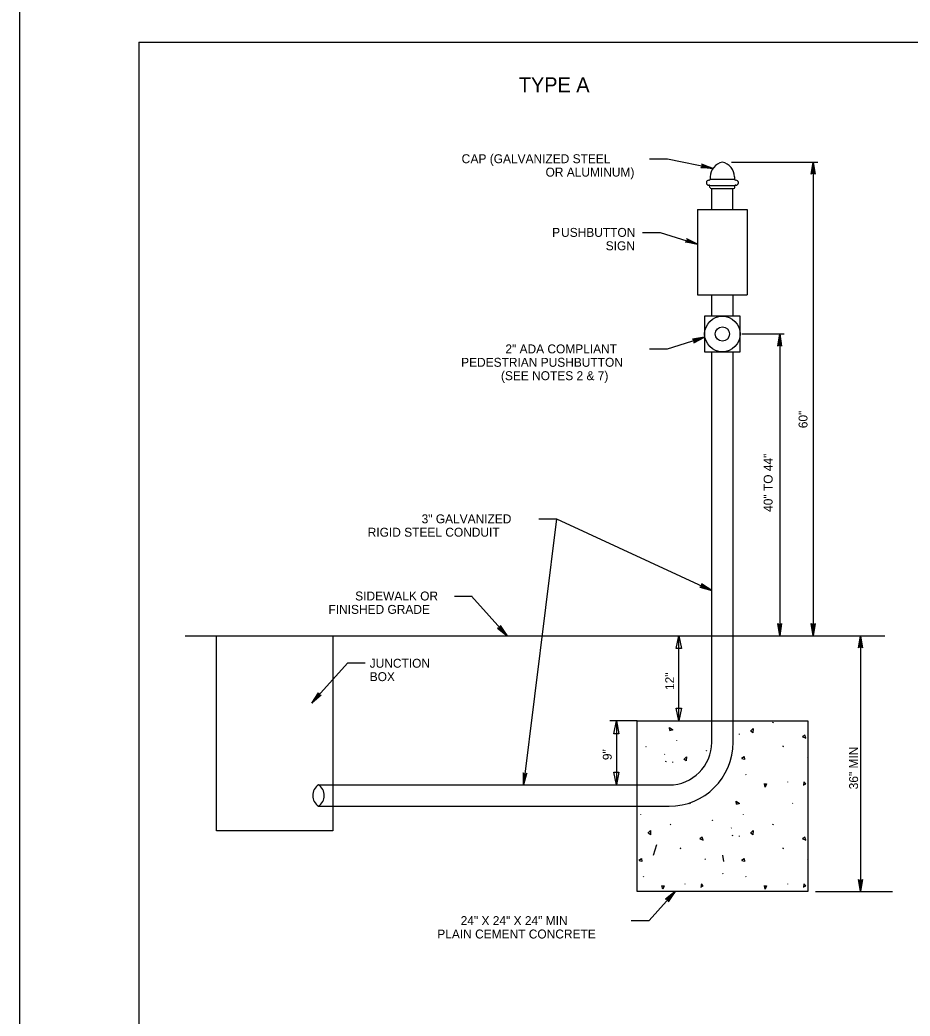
# Model space of a CAD drawing. Extents: x 36 to 940, y -1166 to 1210.
# Drawn here: x 35.9 to 335.1, y 274 to 608.7 of the extents above; entities that cross this region are included whole.
import ezdxf

# ---------------------------------------------------------------- set-up
doc = ezdxf.new("R2010")
doc.units = 0
for name, color, linetype in [('1', 7, 'Continuous'), ('2', 7, 'Continuous'), ('Default', 7, 'Continuous'), ('PLT-BNDY', 7, 'Continuous')]:
    doc.layers.add(name, color=color, linetype=linetype)

msp = doc.modelspace()

# ---------------------------------------------------------------- linework, layer by layer
at = {"layer": '1'}
for q in [(861.86, 601.17), (75.86, 37.17)]:
    msp.add_line((75.86, 601.17), q, dxfattribs=at)
at = {"layer": '2'}
for p, q in [((253.55, 562.03), (268.91, 558.82)), ((251.16, 537.28), (263.67, 533.38)), ((253.55, 498.13), (266.06, 502.03)), ((216.28, 441.04), (205.15, 351.63)), ((216.28, 441.04), (268.4, 416.95)), ((187.65, 415.11), (199.59, 401.8)), ((145.96, 392.51), (134.02, 379.19)), ((247.41, 306.04), (256.12, 315.83))]:
    msp.add_line(p, q, dxfattribs=at)
for points in [[(265.22, 560.07), (265.3, 559.77), (268.89, 558.79), (265.22, 560.07), (265.06, 560.28), (268.89, 558.79), (265.22, 559.39), (265.03, 559.15), (268.89, 558.79), (264.79, 559.01), (265.03, 559.15)], [(302.09, 557.05), (302.37, 557.2), (302.57, 560.91), (302.09, 557.05), (301.92, 556.86), (302.57, 560.91), (302.76, 557.2), (303.03, 557.07), (302.57, 560.91), (303.22, 556.86), (303.03, 557.07)], [(260.14, 535), (260.19, 534.69), (263.67, 533.38), (260.14, 535), (260, 535.22), (263.67, 533.38), (260.08, 534.32), (259.86, 534.1), (263.67, 533.38), (259.61, 533.99), (259.86, 534.1)], [(290.82, 499.29), (291.09, 499.43), (291.3, 503.15), (290.82, 499.29), (290.65, 499.09), (291.3, 503.15), (291.48, 499.44), (291.76, 499.3), (291.3, 503.15), (291.94, 499.09), (291.76, 499.3)], [(262.53, 500.4), (262.58, 500.71), (266.06, 502.03), (262.53, 500.4), (262.39, 500.18), (266.06, 502.03), (262.46, 501.08), (262.25, 501.3), (266.06, 502.03), (262, 501.42), (262.25, 501.3)], [(264.75, 418.12), (264.99, 418.31), (268.45, 416.92), (264.75, 418.12), (264.49, 418.05), (268.45, 416.92), (265.16, 418.66), (265.16, 418.97), (268.45, 416.92), (265.05, 419.23), (265.16, 418.97)], [(196.7, 404.32), (197.01, 404.4), (199.63, 401.76), (196.7, 404.32), (196.44, 404.36), (199.63, 401.76), (197.3, 404.66), (197.42, 404.94), (199.63, 401.76), (197.42, 405.22), (197.42, 404.94)], [(291.78, 405.62), (291.5, 405.48), (291.3, 401.76), (291.78, 405.62), (291.95, 405.82), (291.3, 401.76), (291.12, 405.48), (290.84, 405.61), (291.3, 401.76), (290.65, 405.82), (290.84, 405.61)], [(303.06, 405.62), (302.78, 405.48), (302.57, 401.76), (303.06, 405.62), (303.23, 405.82), (302.57, 401.76), (302.39, 405.48), (302.11, 405.61), (302.57, 401.76), (301.93, 405.82), (302.11, 405.61)], [(317.96, 397.9), (318.24, 398.05), (318.44, 401.76), (317.96, 397.9), (317.79, 397.71), (318.44, 401.76), (318.63, 398.05), (318.9, 397.91), (318.44, 401.76), (319.09, 397.71), (318.9, 397.91)], [(136.91, 381.71), (136.6, 381.79), (133.98, 379.15), (136.91, 381.71), (137.17, 381.75), (133.98, 379.15), (136.31, 382.05), (136.19, 382.33), (133.98, 379.15), (136.19, 382.61), (136.19, 382.33)], [(205.18, 355.52), (205.44, 355.34), (205.15, 351.63), (205.18, 355.52), (205.04, 355.74), (205.15, 351.63), (205.82, 355.29), (206.12, 355.38), (205.15, 351.63), (206.33, 355.57), (206.12, 355.38)], [(318.93, 319.68), (318.65, 319.54), (318.44, 315.82), (318.93, 319.68), (319.1, 319.88), (318.44, 315.82), (318.26, 319.53), (317.98, 319.67), (318.44, 315.82), (317.8, 319.88), (317.98, 319.67)], [(253.93, 312.61), (253.81, 312.91), (256.12, 315.83), (253.93, 312.61), (253.92, 312.35), (256.12, 315.83), (253.52, 313.17), (253.23, 313.25), (256.12, 315.83), (252.95, 313.21), (253.23, 313.25)]]:
    msp.add_lwpolyline(points, dxfattribs=at)
at = {"layer": 'Default'}
for p, q in [((247.55, 562.03), (253.55, 562.03)), ((275.11, 560.91), (304.07, 560.91)), ((267.97, 555.96), (267.97, 555.22)), ((276.09, 555.96), (276.09, 555.22)), ((302.57, 558.13), (302.57, 401.76)), ((267.49, 554.82), (267.55, 554.82)), ((267.65, 553.13), (267.49, 553.13)), ((267.86, 552.38), (267.86, 552.93)), ((276.19, 552.38), (276.19, 552.93)), ((276.56, 553.13), (276.4, 553.13)), ((276.5, 554.82), (276.56, 554.82)), ((277.4, 553.92), (277.4, 554.03)), ((268.28, 551.98), (275.78, 551.98)), ((268.52, 545), (268.52, 551.98)), ((275.53, 545), (275.53, 551.98)), ((263.67, 545), (280.38, 545)), ((263.67, 545), (263.67, 516.35)), ((280.38, 545), (280.38, 516.35)), ((245.16, 537.28), (251.16, 537.28)), ((263.67, 516.35), (280.38, 516.35)), ((278.53, 503.15), (292.8, 503.15)), ((291.3, 503.15), (291.3, 401.76)), ((247.55, 498.13), (253.55, 498.13)), ((266.06, 497.18), (278, 497.18)), ((268.45, 401.76), (268.45, 497.18)), ((275.61, 401.76), (275.61, 497.18)), ((210.28, 441.04), (216.28, 441.04)), ((181.95, 415.11), (187.95, 415.11)), ((257.37, 373.12), (257.37, 401.76)), ((268.45, 365.95), (268.45, 401.76)), ((275.61, 365.95), (275.61, 401.76)), ((299.72, 401.76), (307.48, 401.76)), ((318.44, 401.76), (318.44, 315.82)), ((151.96, 392.51), (145.96, 392.51)), ((243.41, 373.12), (234.24, 373.12)), ((236.39, 373.12), (236.39, 351.63)), ((288.97, 372.55), (289.14, 372.69)), ((289.14, 372.69), (289, 372.48)), ((277.83, 368.61), (277.79, 368.83)), ((256.67, 366.45), (256.71, 366.59)), ((243.47, 364.52), (243.54, 364.59)), ((246.43, 364.44), (246.25, 364.48)), ((246.32, 364.59), (246.43, 364.44)), ((252.56, 361.9), (252.63, 361.97)), ((266.55, 363.08), (266.73, 363.23)), ((266.73, 363.23), (266.59, 363.01)), ((292.33, 364.64), (292.55, 364.53)), ((292.58, 364.53), (292.37, 364.71)), ((253.05, 359.36), (253.16, 359.72)), ((255.42, 359.14), (255.38, 359.36)), ((300.7, 360.93), (300.6, 361.02)), ((280.05, 354.93), (279.94, 355.15)), ((136.24, 351.63), (254.12, 351.63)), ((294.01, 352.6), (294.01, 352.68)), ((261.09, 345.36), (261.27, 345.5)), ((295.58, 345.36), (295.76, 345.5)), ((136.24, 344.47), (254.12, 344.47)), ((244.6, 341.65), (244.63, 341.79)), ((279.08, 341.65), (279.12, 341.79)), ((254.48, 338.28), (254.66, 338.42)), ((254.66, 338.42), (254.52, 338.21)), ((268.66, 339.71), (268.73, 339.79)), ((268.84, 339.64), (268.66, 339.68)), ((268.73, 339.79), (268.84, 339.64)), ((288.97, 338.28), (289.14, 338.42)), ((289.14, 338.42), (289, 338.21)), ((274.97, 337.1), (275.04, 337.17)), ((275.47, 334.56), (275.57, 334.92)), ((248.91, 328.05), (249.99, 331.63)), ((277.83, 334.34), (277.79, 334.56)), ((257.85, 330.37), (258.06, 330.26)), ((258.1, 330.26), (257.88, 330.44)), ((272.55, 325.9), (272.19, 328.05)), ((292.33, 330.37), (292.55, 330.26)), ((292.58, 330.26), (292.37, 330.44)), ((266.33, 326.57), (266.11, 326.75)), ((300.7, 326.66), (300.6, 326.75)), ((272.1, 321.77), (272.17, 321.92)), ((272.17, 321.92), (272.17, 321.74)), ((245.57, 320.66), (245.46, 320.88)), ((259.53, 318.34), (259.53, 318.41)), ((280.05, 320.66), (279.94, 320.88)), ((294.01, 318.34), (294.01, 318.41)), ((303.33, 315.82), (329.25, 315.82)), ((241.41, 306.04), (247.41, 306.04))]:
    msp.add_line(p, q, dxfattribs=at)
for points in [[(268.45, 509.12), (268.45, 516.35)], [(275.61, 509.12), (275.61, 516.35)], [(278, 497.18), (278, 509.12), (266.06, 509.12), (266.06, 497.18), (266.06, 497.18)], [(91.44, 401.76), (275.61, 401.76), (326.66, 401.76)], [(141.07, 401.76), (141.07, 336.24), (101.93, 336.24), (101.93, 401.76), (141.07, 401.76)], [(243.41, 373.12), (300.7, 373.12), (300.7, 315.82), (243.41, 315.82), (243.41, 373.12)], [(254.31, 369.96), (254.24, 370.96), (255.38, 370.14), (254.24, 369.81)], [(281.48, 369.69), (282.38, 370.58), (282.31, 369.18), (281.62, 369.69)], [(298.85, 367.86), (300.07, 367.36), (299.74, 368.32), (298.99, 367.93)], [(259.07, 360.22), (259.97, 361.11), (259.89, 359.72), (259.21, 360.22)], [(278.44, 360.63), (279.33, 361.2), (279.44, 360.16), (278.55, 360.41)], [(285.99, 352.03), (286.89, 352.03), (286.46, 350.89), (286.14, 351.96)], [(299.34, 351.66), (300.09, 352.05), (299.44, 352.62), (299.26, 351.48)], [(276.72, 345.16), (276.65, 346.16), (277.79, 345.34), (276.65, 345.01)], [(247, 335.42), (247.89, 336.31), (247.82, 334.92), (247.14, 335.42)], [(281.48, 335.42), (282.38, 336.31), (282.31, 334.92), (281.62, 335.42)], [(264.37, 333.59), (265.58, 333.09), (265.26, 334.06), (264.51, 333.66)], [(298.85, 333.59), (300.07, 333.09), (299.74, 334.06), (298.99, 333.66)], [(243.95, 326.36), (244.85, 326.93), (244.96, 325.89), (244.06, 326.14)], [(278.44, 326.36), (279.33, 326.93), (279.44, 325.89), (278.55, 326.14)], [(264.85, 317.39), (265.6, 317.78), (264.96, 318.36), (264.78, 317.21)], [(299.34, 317.39), (300.09, 317.78), (299.44, 318.36), (299.26, 317.21)], [(251.51, 317.76), (252.4, 317.76), (251.98, 316.62), (251.65, 317.69)], [(285.99, 317.76), (286.89, 317.76), (286.46, 316.62), (286.14, 317.69)]]:
    msp.add_lwpolyline(points, dxfattribs=at)
for points in [[(256.51, 397.47), (257.37, 401.76), (258.23, 397.47)], [(258.23, 377.41), (257.37, 373.12), (256.51, 377.41)], [(235.53, 368.82), (236.39, 373.12), (237.25, 368.82)], [(237.25, 355.93), (236.39, 351.63), (235.53, 355.93)]]:
    msp.add_lwpolyline(points, close=True, dxfattribs=at)
for radius in [5.97, 2.39]:
    msp.add_circle((272.03, 503.15), radius, dxfattribs=at)
for centre, radius, start, end in [((254.12, 365.95), 14.32, 270, 0), ((254.12, 365.95), 21.49, 270, 0), ((138.62, 348.05), 4.3, 123.5573, 236.4427), ((133.86, 348.05), 4.3, 303.5573, 56.4427)]:
    msp.add_arc(centre, radius, start, end, dxfattribs=at)
for centre, major_axis, ratio, start_param, end_param in [((273.39, 555.91), (5.43, 0), 0.952381, 1.825494, 3.132766), ((270.66, 555.91), (5.43, 0), 0.952381, 0.008827, 1.316099), ((267.49, 554.03), (0.833, 0), 0.952381, 1.570796, 3.141593), ((267.49, 553.92), (0.833, 0), 0.952381, 3.141593, 4.712389), ((267.55, 555.22), (0.417, 0), 0.952381, 4.712389, 6.283185), ((267.65, 552.93), (0.208, 0), 0.952381, 0, 1.570796), ((272.11, 553.13), (-4.46, 0), 0.026054, 0.212556, 2.780907), ((268.28, 552.38), (0.417, 0), 0.952381, 3.141593, 4.712389), ((272.03, 555.22), (-4.06, 0), 0.012269, 0, 3.141593), ((275.78, 552.38), (0.417, 0), 0.952381, 4.712389, 6.283185), ((276.5, 555.22), (0.417, 0), 0.952381, 3.141593, 4.712389), ((276.4, 552.93), (0.208, 0), 0.952381, 1.570796, 3.141593), ((276.56, 554.03), (0.833, 0), 0.952381, 0, 1.570796), ((276.56, 553.92), (0.833, 0), 0.952381, 4.712389, 6.283185)]:
    msp.add_ellipse(centre, major_axis=major_axis, ratio=ratio, start_param=start_param, end_param=end_param, dxfattribs=at)
at = {"layer": 'PLT-BNDY'}
msp.add_lwpolyline([(35.86, 616.17), (876.86, 616.17), (876.86, 22.17), (35.86, 22.17)], close=True, dxfattribs=at)

# ---------------------------------------------------------------- texts
at = {"layer": '2'}
msp.add_text('TYPE A', height=5, dxfattribs=at).set_placement((203.59, 584.39))
at = {"layer": 'Default'}
for s, rotation, p in [('C', 360, (184.35, 560.53)), ('AP (GALVANIZED STEEL', 360, (187.35, 560.53)), ('OR ALUMINUM)', 360, (212.58, 556.03)), ('P', 360, (214.8, 535.78)), ('USHBUTTON', 360, (217.8, 535.78)), ('SIGN', 360, (232.8, 531.28)), ('2" ADA COMPLIANT', 360, (199.07, 496.63)), ('PEDESTRIAN PUSHBUTTON', 360, (184.19, 492.13)), ('(SEE NOTES 2 & 7)', 360, (197.58, 487.63)), (' 60"', 90, (300.64, 470.38)), ('40" TO 44"', 90, (288.91, 443.37)), ('3" GALVANIZED', 360, (170.91, 439.54)), ('RIGID STEEL CONDUIT', 360, (152.79, 435.04)), ('SIDEWALK OR', 360, (148.58, 413.61)), ('FINISHED GRADE', 360, (139.6, 409.11)), ('JUNCTION ', 360, (153.46, 391.01)), ('BOX', 360, (153.46, 386.51)), ('12"', 90, (255.81, 383.53)), ('9"', 90, (234.83, 359.96)), ('36" MIN', 90, (317.64, 350.16)), ('24" X 24" X 24" MIN', 360, (184.04, 304.54)), (' PLAIN CEMENT CONCRETE', 360, (175.06, 300.04))]:
    msp.add_text(s, height=3, rotation=rotation, dxfattribs=at).set_placement(p)

doc.saveas('drawing.dxf')
